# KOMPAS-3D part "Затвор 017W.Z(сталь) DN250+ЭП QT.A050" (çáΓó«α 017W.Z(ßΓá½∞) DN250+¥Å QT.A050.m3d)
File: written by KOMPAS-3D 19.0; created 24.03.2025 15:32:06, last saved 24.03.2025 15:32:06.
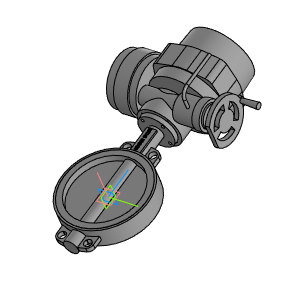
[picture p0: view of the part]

Document properties: Полное имя файла: Затвор 017W.Z(сталь) DN250+ЭП QT.A050.a3d

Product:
- Part/product: Затвор 017W.Z(сталь) DN250+ЭП QT.A050
    Масса: 139.528

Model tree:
1. Операция без истории:1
